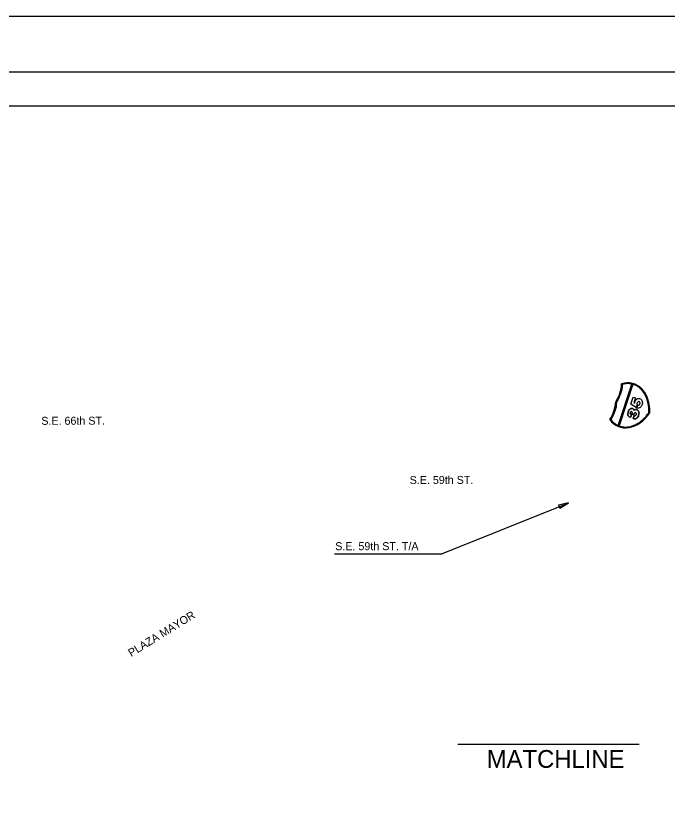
# Model space of a CAD drawing. Extents: x 2143531 to 2162022, y 139508 to 147626.
# Drawn here: x 2151304 to 2154561, y 143608 to 147626 of the extents above; entities that cross this region are included whole.
import ezdxf

# ---------------------------------------------------------------- set-up
doc = ezdxf.new("R2010")
doc.units = 0
for name, color, linetype in [('5', 7, 'Continuous'), ('7', 7, 'Continuous'), ('Default', 7, 'Continuous'), ('PR_Phasing_Pavement_2', 7, 'Continuous'), ('PR_Shading_Bridge_Phase_4', 7, 'Continuous'), ('SHT_Plot_Shape_Full', 7, 'Continuous'), ('SHT_Plot_Shape_Half', 7, 'Continuous'), ('SHT_Sheet_Border', 7, 'Continuous')]:
    doc.layers.add(name, color=color, linetype=linetype)

# ---------------------------------------------------------------- blocks, each defined once
blk = doc.blocks.new('ARROWHD')
at = {"layer": 'Default'}
blk.add_lwpolyline([(0.313, -0.054), (0.313, 0.052), (-0.005, -0.001)], close=True, dxfattribs=at)
blk = doc.blocks.new('i-35-shield')
at = {"layer": '7'}
blk.add_line((-18.46, 5.36), (18.44, 5.36), dxfattribs=at)
blk.add_line((-18.46, 5.36), (18.44, 5.36), dxfattribs=at)
for points in [[(-18.51, 4.66), (-18.53, 3.83), (-18.52, 3.24), (-18.48, 2.57), (-18.35, 1.51), (-18.16, 0.52), (-17.93, -0.38), (-17.62, -1.35), (-17.14, -2.55), (-16.62, -3.61), (-15.87, -4.91), (-15.07, -6.06), (-14.15, -7.22), (-13.32, -8.14), (-12.31, -9.13), (-11.77, -9.61), (-10.87, -10.36), (-9.96, -11.05), (-8.99, -11.73), (-7.81, -12.47), (-6.93, -12.98), (-5.68, -13.64), (-4.12, -14.37), (-3.06, -14.81), (-1.71, -15.32), (-0.77, -15.63), (-0.01, -15.87), (0.75, -15.63), (1.69, -15.32), (3.04, -14.81), (4.1, -14.37), (5.66, -13.64), (6.9, -12.98), (7.78, -12.47), (8.96, -11.73), (9.93, -11.05), (10.85, -10.36), (11.74, -9.61), (12.28, -9.13), (13.29, -8.14), (14.13, -7.22), (15.05, -6.06), (15.84, -4.91), (16.6, -3.61), (17.12, -2.55), (17.6, -1.35), (17.91, -0.38), (18.14, 0.52), (18.33, 1.51), (18.45, 2.57), (18.5, 3.24), (18.51, 3.83), (18.49, 4.66), (-18.51, 4.66)], [(-8.85, -4.7), (-6.35, -4.7), (-6.35, -5.22), (-6.27, -5.4), (-6.19, -5.55), (-5.93, -5.9), (-5.48, -6.12), (-5.31, -6.2), (-5.05, -6.27), (-4.61, -6.27), (-4.2, -6.2), (-3.69, -5.78), (-3.55, -5.47), (-3.55, -5.11), (-3.78, -4.71), (-3.93, -4.59), (-4.19, -4.44), (-4.63, -4.3), (-5.84, -4.3), (-5.84, -2.63), (-4.61, -2.63), (-4.28, -2.55), (-4.07, -2.43), (-3.8, -2.06), (-3.75, -1.98), (-3.75, -1.63), (-3.9, -1.39), (-4.06, -1.19), (-4.27, -1.07), (-4.61, -1), (-5.05, -1), (-5.51, -1.15), (-5.66, -1.22), (-6, -1.49), (-6.07, -1.61), (-6.24, -1.97), (-6.24, -2.47), (-8.54, -2.47), (-8.54, -1.24), (-8.42, -0.82), (-8.18, -0.41), (-7.93, -0.11), (-7.24, 0.46), (-6.77, 0.66), (-6.1, 0.84), (-5.44, 0.94), (-4.02, 0.94), (-2.69, 0.57), (-2, 0.19), (-1.74, -0.02), (-1.52, -0.32), (-1.15, -0.82), (-1.04, -1.52), (-1.04, -1.88), (-1.28, -2.47), (-1.4, -2.68), (-1.64, -2.99), (-2.01, -3.29), (-2.13, -3.35), (-1.79, -3.54), (-1.55, -3.76), (-1.18, -4.16), (-0.94, -4.75), (-0.83, -5.14), (-0.83, -5.58), (-1.06, -6.44), (-1.3, -6.85), (-1.54, -7.15), (-2, -7.54), (-2.35, -7.73), (-2.91, -8.02), (-3.7, -8.2), (-4.67, -8.3), (-5.55, -8.3), (-6.88, -8.02), (-7.68, -7.54), (-8.03, -7.25), (-8.37, -6.87), (-8.61, -6.56), (-8.85, -5.77), (-8.85, -4.7)], [(3.79, -2.06), (4.08, -1.94), (4.66, -1.84), (5.66, -1.84), (6.21, -1.93), (6.65, -2.03), (7.12, -2.22), (7.58, -2.51), (7.93, -2.79), (8.27, -3.18), (8.51, -3.57), (8.73, -4.03), (8.86, -4.45), (8.86, -5.42), (8.73, -5.84), (8.51, -6.3), (8.26, -6.71), (7.92, -6.99), (7.48, -7.45), (6.9, -7.74), (6.26, -8.01), (5.7, -8.2), (4.92, -8.3), (4.25, -8.3), (3.59, -8.2), (2.93, -8.02), (2.38, -7.83), (1.81, -7.55), (1.24, -7.07), (0.76, -6.47), (0.52, -5.68), (0.52, -5.05), (2.93, -5.05), (3.1, -5.49), (3.37, -5.94), (3.61, -6.14), (3.95, -6.29), (4.21, -6.35), (4.86, -6.35), (5.12, -6.28), (5.57, -6.13), (5.9, -5.85), (5.97, -5.74), (6.14, -5.39), (6.14, -4.82), (6.07, -4.64), (5.9, -4.36), (5.57, -4.09), (5.12, -3.94), (4.86, -3.86), (4.22, -3.86), (3.96, -3.93), (3.79, -4.01), (3.56, -4.13), (3.42, -4.39), (0.86, -4.39), (2.04, 0.85), (8.33, 0.85), (8.33, -1.17), (4, -1.17), (3.79, -2.06)]]:
    blk.add_lwpolyline(points, dxfattribs=at)
for points in [[(-18.51, 4.66), (-18.53, 3.83), (-18.52, 3.24), (-18.48, 2.57), (-18.35, 1.51), (-18.16, 0.52), (-17.93, -0.38), (-17.62, -1.35), (-17.14, -2.55), (-16.62, -3.61), (-15.87, -4.91), (-15.07, -6.06), (-14.15, -7.22), (-13.32, -8.14), (-12.31, -9.13), (-11.77, -9.61), (-10.87, -10.36), (-9.96, -11.05), (-8.99, -11.73), (-7.81, -12.47), (-6.93, -12.98), (-5.68, -13.64), (-4.12, -14.37), (-3.06, -14.81), (-1.71, -15.32), (-0.77, -15.63), (-0.01, -15.87), (0.75, -15.63), (1.69, -15.32), (3.04, -14.81), (4.1, -14.37), (5.66, -13.64), (6.9, -12.98), (7.78, -12.47), (8.96, -11.73), (9.93, -11.05), (10.85, -10.36), (11.74, -9.61), (12.28, -9.13), (13.29, -8.14), (14.13, -7.22), (15.05, -6.06), (15.84, -4.91), (16.6, -3.61), (17.12, -2.55), (17.6, -1.35), (17.91, -0.38), (18.14, 0.52), (18.33, 1.51), (18.45, 2.57), (18.5, 3.24), (18.51, 3.83), (18.49, 4.66)], [(-8.85, -5.77), (-8.61, -6.56), (-8.37, -6.87), (-8.03, -7.25), (-7.68, -7.54), (-6.88, -8.02), (-5.55, -8.3), (-4.67, -8.3), (-3.7, -8.2), (-2.91, -8.02), (-2.35, -7.73), (-2, -7.54), (-1.54, -7.15), (-1.3, -6.85), (-1.06, -6.44), (-0.83, -5.58), (-0.83, -5.14), (-0.94, -4.75), (-1.18, -4.16), (-1.55, -3.76), (-1.79, -3.54), (-2.13, -3.35), (-2.01, -3.29), (-1.64, -2.99), (-1.4, -2.68), (-1.28, -2.47), (-1.04, -1.88), (-1.04, -1.52), (-1.15, -0.82), (-1.52, -0.32), (-1.74, -0.02), (-2, 0.19), (-2.69, 0.57), (-4.02, 0.94), (-5.44, 0.94), (-6.1, 0.84), (-6.77, 0.66), (-7.24, 0.46), (-7.93, -0.11), (-8.18, -0.41), (-8.42, -0.82), (-8.54, -1.24), (-8.54, -2.47), (-6.24, -2.47), (-6.24, -1.97), (-6.07, -1.61), (-6, -1.49), (-5.66, -1.22), (-5.51, -1.15), (-5.05, -1), (-4.61, -1), (-4.27, -1.07), (-4.06, -1.19), (-3.9, -1.39), (-3.75, -1.63), (-3.75, -1.98), (-3.8, -2.06), (-4.07, -2.43), (-4.28, -2.55), (-4.61, -2.63), (-5.84, -2.63), (-5.84, -4.3), (-4.63, -4.3), (-4.19, -4.44), (-3.93, -4.59), (-3.78, -4.71), (-3.55, -5.11), (-3.55, -5.47), (-3.69, -5.78), (-4.2, -6.2), (-4.61, -6.27), (-5.05, -6.27), (-5.31, -6.2), (-5.48, -6.12), (-5.93, -5.9), (-6.19, -5.55), (-6.27, -5.4), (-6.35, -5.22), (-6.35, -4.7), (-8.85, -4.7)], [(3.79, -2.06), (4.08, -1.94), (4.66, -1.84), (5.66, -1.84), (6.21, -1.93), (6.65, -2.03), (7.12, -2.22), (7.58, -2.51), (7.93, -2.79), (8.27, -3.18), (8.51, -3.57), (8.73, -4.03), (8.86, -4.45), (8.86, -5.42), (8.73, -5.84), (8.51, -6.3), (8.26, -6.71), (7.92, -6.99), (7.48, -7.45), (6.9, -7.74), (6.26, -8.01), (5.7, -8.2), (4.92, -8.3), (4.25, -8.3), (3.59, -8.2), (2.93, -8.02), (2.38, -7.83), (1.81, -7.55), (1.24, -7.07), (0.76, -6.47), (0.52, -5.68), (0.52, -5.05), (2.93, -5.05), (3.1, -5.49), (3.37, -5.94), (3.61, -6.14), (3.95, -6.29), (4.21, -6.35), (4.86, -6.35), (5.12, -6.28), (5.57, -6.13), (5.9, -5.85), (5.97, -5.74), (6.14, -5.39), (6.14, -4.82), (6.07, -4.64), (5.9, -4.36), (5.57, -4.09), (5.12, -3.94), (4.86, -3.86), (4.22, -3.86), (3.96, -3.93), (3.79, -4.01), (3.56, -4.13), (3.42, -4.39), (0.86, -4.39), (2.04, 0.85), (8.33, 0.85), (8.33, -1.17), (4, -1.17)]]:
    blk.add_lwpolyline(points, close=True, dxfattribs=at)
for centre, major_axis, start_param, end_param in [((11.77, 3.87), (31.01, 0), 2.678593, 4.322471), ((-7.87, 27.69), (-21.16, 0), 1.177968, 1.951302), ((-11.8, 3.87), (-31.01, 0), 1.960714, 3.604592), ((7.85, 27.69), (21.16, 0), 4.331883, 5.105218)]:
    blk.add_ellipse(centre, major_axis=major_axis, ratio=0.713476, start_param=start_param, end_param=end_param, dxfattribs=at)
for points in [[(-15.68, 12.94), (-16.64, 11.49), (-17.36, 9.97), (-18.15, 7.41), (-18.36, 6.39), (-18.46, 5.36)], [(-15.68, 12.94), (-16.64, 11.49), (-17.36, 9.97), (-18.15, 7.41), (-18.36, 6.39), (-18.46, 5.36)], [(-15.68, 12.94), (-14.13, 12.51), (-12.51, 12.21), (-7.22, 11.69), (-3.45, 12), (-0.01, 12.95)], [(-0.01, 12.95), (-3.45, 12), (-7.22, 11.69), (-12.51, 12.21), (-14.13, 12.51), (-15.68, 12.94)], [(-0.01, 12.95), (1.63, 12.5), (3.36, 12.18), (8.65, 11.7), (12.31, 12.02), (15.65, 12.94)], [(15.65, 12.94), (12.31, 12.02), (8.65, 11.7), (3.36, 12.18), (1.63, 12.5), (-0.01, 12.95)], [(18.44, 5.36), (18.35, 6.27), (18.18, 7.17), (17.45, 9.74), (16.68, 11.38), (15.65, 12.94)], [(18.44, 5.36), (18.35, 6.27), (18.18, 7.17), (17.45, 9.74), (16.68, 11.38), (15.65, 12.94)]]:
    blk.add_open_spline(points, degree=3, dxfattribs=at)

msp = doc.modelspace()

# ---------------------------------------------------------------- linework, layer by layer
at = {"layer": '5'}
for p in [(2154064.1, 145192.1), (2152895.9, 144938.3)]:
    msp.add_line(p, (2153433.5, 144938.3), dxfattribs=at)
at = {"layer": '7'}
msp.add_lwpolyline([(2154313, 145579.7), (2154316.8, 145578.1), (2154385.2, 145785.6), (2154381.1, 145786.6)], close=True, dxfattribs=at)
at = {"layer": 'PR_Phasing_Pavement_2'}
msp.add_line((2153511.8, 143987.4), (2154417.9, 143987.4), dxfattribs=at)
at = {"layer": 'SHT_Plot_Shape_Full'}
msp.add_lwpolyline([(2144487.6, 147626.1), (2156665.5, 147626.1), (2156665.5, 139507.5), (2144487.6, 139507.5)], close=True, dxfattribs=at)
at = {"layer": 'SHT_Plot_Shape_Half'}
msp.add_lwpolyline([(2145041.6, 147347.1), (2156542.9, 147347.1), (2156542.9, 139905), (2145041.6, 139905)], close=True, dxfattribs=at)
at = {"layer": 'SHT_Sheet_Border'}
msp.add_lwpolyline([(2156356.9, 140074.1), (2145701.2, 140074.1), (2145701.2, 147177.9), (2156356.9, 147177.9)], close=True, dxfattribs=at)

# ---------------------------------------------------------------- block references
at = {"layer": '5', "xscale": 157.48000000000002, "yscale": 157.47999999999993, "rotation": -158.08307391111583}
msp.add_blockref('ARROWHD', (2154064.1, 145192.1), dxfattribs=at)
at = {"layer": '7', "xscale": 5.905500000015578, "yscale": 5.905500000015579, "rotation": 71.78521686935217}
msp.add_blockref('i-35-shield', (2154377.2, 145673.3), dxfattribs=at)

# ---------------------------------------------------------------- texts
at = {"layer": 'PR_Phasing_Pavement_2'}
msp.add_text('MATCHLINE', height=89.02, dxfattribs=at).set_placement((2153656.3, 143868.2))
at = {"layer": 'PR_Shading_Bridge_Phase_4'}
for s, rotation, p in [('S.E. 66th ST.', 0.1579, (2151430.3, 145582.9)), ('S.E. 59th ST.', 0.1579, (2153270.9, 145286.9)), ('PLAZA MAYOR', 31.6564, (2151879.7, 144421.8))]:
    msp.add_text(s, height=40, rotation=rotation, dxfattribs=at).set_placement(p)
msp.add_text('S.E. 59th ST. T/A', height=40, dxfattribs=at).set_placement((2152898.9, 144956.4))

doc.saveas('drawing.dxf')
